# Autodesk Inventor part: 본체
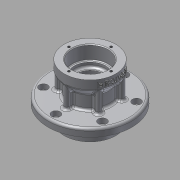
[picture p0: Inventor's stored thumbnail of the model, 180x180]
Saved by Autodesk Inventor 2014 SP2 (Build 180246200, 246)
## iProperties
Created: 2024-04
Part Number: 본체
Material: 알루미늄 6061
Document SubType Name: Modeling
Designer: Administrator
Density: 2.71 g/cm^3
Appearance: 알루미늄 - 평지
Mass: 492.903 g
Surface Area: 449.917 cm^2
Volume: 181.883 cm^3
Author: Administrator
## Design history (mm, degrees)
sketch "스케치1"
  geometry: L1 (-76.3, 0)-(76.3, 0) reference; L2 (0, -76.3)-(0, 76.3) reference; C1 r 54.5 at (0, 0); 1 further point
  constraints: 1 centre point, 1 coincident
  dimensions: "d0" = 109 diameter of C1
extrude "돌출1" new body sketch "스케치1" distance "d1" = 10; taper "d2" = 0 deg
sketch "스케치2"
  geometry: C1 r 54.5 at (0, 0) reference; C2 r 38.5 at (0, 0)
  constraints: 1 centre point, 1 coincident
  dimensions: "d3" = 77 diameter of C2
extrude "돌출2" join sketch "스케치2" distance "d4" = 5; taper "d5" = 0 deg
sketch "스케치3"
  geometry: C1 r 38.5 at (0, 0) reference; C2 r 33.5 at (0, 0)
  constraints: 1 centre point, 1 coincident
  dimensions: "d6" = 67 diameter of C2
extrude "돌출3" join sketch "스케치3" distance "d7" = 15; taper "d8" = 0 deg
node "작업 평면1"
sketch "스케치8"
  geometry: L1 (0, 0)-(0, 72.039); L2 (54.5, 10)-(-54.5, 10) reference; L3 (25.5, 10)-(25.5, 28.121); L4 (25.5, 28.121)-(33.5, 38); L5 (33.5, 38)-(33.5, 50); L6 (33.5, 50)-(0, 50); L7 (25.5, 10)-(0, 10); L8 (0, 50)-(0, 10)
  constraints: 14 end point, 2 perpendicular, 2 point on line, 1 collinear, 1 midpoint, 1 parallel, 1 vertical
  dimensions: "d21" = 67 diameter of L5.end L1; "d22" = 12 distance of L4.end L5.end; "d23" = 39 deg angle of L5 L4; "d24" = 40 distance from line of L3.start L6; "d25" = 51 diameter of L3 L1
revolve "회전1" sketch "스케치8" stored, may be unused: angle "d26" = 90 deg
node "작업 평면2"
sketch "스케치9"
  geometry: L1 (-76.3, 0)-(76.3, 0) reference; L2 (0, -76.3)-(0, 76.3) reference; L3 (0, 20.5)-(0, 30.5); L4 (3, 20.5)-(3, 30.5); L5 (-3, 30.5)-(-3, 20.5); L6 (-13.675, 33.5)-(11.062, 33.5); L7 (-16.254, 12.848)-(-24.914, 17.848); L8 (-27.914, 12.652)-(-19.254, 7.652); L9 (-19.254, -7.652)-(-27.914, -12.652); L10 (-24.914, -17.848)-(-16.254, -12.848); L11 (-3, -20.5)-(-3, -30.5); L12 (3, -30.5)-(3, -20.5); L13 (16.254, -12.848)-(24.914, -17.848); L14 (27.914, -12.652)-(19.254, -7.652); L15 (19.254, 7.652)-(27.914, 12.652); L16 (24.914, 17.848)-(16.254, 12.848); A1 r 3 centre (0, 20.5) between (-3, 20.5) and (3, 20.5); A2 r 3 centre (0, 30.5) between (3, 30.5) and (-3, 30.5); A3 r 3 centre (-26.414, 15.25) between (-24.914, 17.848) and (-27.914, 12.652); A4 r 3 centre (-17.754, 10.25) between (-19.254, 7.652) and (-16.254, 12.848); A5 r 3 centre (-26.414, -15.25) between (-27.914, -12.652) and (-24.914, -17.848); A6 r 3 centre (-17.754, -10.25) between (-16.254, -12.848) and (-19.254, -7.652); A7 r 3 centre (0, -30.5) between (-3, -30.5) and (3, -30.5); A8 r 3 centre (0, -20.5) between (3, -20.5) and (-3, -20.5); A9 r 3 centre (26.414, -15.25) between (24.914, -17.848) and (27.914, -12.652); A10 r 3 centre (17.754, -10.25) between (19.254, -7.652) and (16.254, -12.848); A11 r 3 centre (26.414, 15.25) between (27.914, 12.652) and (24.914, 17.848); A12 r 3 centre (17.754, 10.25) between (16.254, 12.848) and (19.254, 7.652); 3 further points
  constraints: 30 end point, 24 point on circle, 12 centre point, 5 tangent, 2 point on line, 1 midpoint, 1 parallel, 1 perpendicular, 1 vertical alignment, 62 other
  dimensions: "d36" = 6 diameter of A2; "d37" = 33.5 distance from line of point (0, 0) L6; "d40" = 360 deg dimension on point (0, 0) L4.start (derived)
extrude "돌출5" join sketch "스케치9" stored distance "d42" = 0; taper "d43" = 0 deg
extrude "돌출6" join sketch "스케치9" stored distance "d44" = 20; taper "d45" = 0 deg
sketch "스케치10"
  geometry: L1 (-33.5, -20)-(33.5, -20) reference; L2 (-33.5, 50)-(33.5, 50) reference; L3 (0, -34)-(0, 64) reference; L4 (23.5, 50)-(0, 50); L5 (0, 50)-(0, 32); L6 (0, 32)-(23.5, 32); L7 (23.5, 32)-(23.5, 50); L8 (20.5, 32)-(0, 32); L9 (0, 32)-(0, 26); L10 (0, 26)-(20.5, 26); L11 (20.5, 26)-(20.5, 32); L12 (16, 26)-(0, 26); L13 (0, 26)-(0, 4); L14 (0, 4)-(16, 4); L15 (16, 4)-(16, 26); L16 (0, 4)-(20.5, 4); L17 (20.5, 4)-(20.5, -2); L18 (20.5, -2)-(0, -2); L19 (0, -2)-(0, 4); L20 (0, -2)-(23.5, -2); L21 (23.5, -2)-(23.5, -20); L22 (23.5, -20)-(0, -20); L23 (0, -20)-(0, -2); 1 further point
  constraints: 40 end point, 10 parallel, 7 point on line, 5 horizontal, 5 perpendicular
  dimensions: "d46" = 47 diameter of L7 L3; "d47" = 18 distance of L6.end L4.start; "d48" = 41 diameter of L11 L3; "d49" = 6 distance of L10.end L8.start; "d50" = 32 diameter of L15 L3; "d51" = 22 distance of L14.end L12.start; "d52" = 41 diameter of L17 L3; "d53" = 6 distance of L16.end L17.end; "d54" = 47 diameter of L21 L3
revolve "회전2" sketch "스케치10" stored, may be unused: angle "d55" = 90 deg
fillet "모깎기1" dims "d56" = 3
fillet "모깎기2" dims "d57" = 3
fillet "모깎기3" dims "d58" = 3
chamfer "모따기1" distance "d59" = 1; stored, may be unused: second distance "d60" = 2, angle "d61" = 45 deg
fillet "모깎기4" dims "d62" = 3
chamfer "모따기2" distance "d63" = 1; stored, may be unused: second distance "d64" = 2, angle "d65" = 45 deg
fillet "모깎기5" dims "d66" = 3
fillet "모깎기6" dims "d67" = 1
fillet "모깎기7" dims "d68" = 3
sketch "스케치12"
  geometry: L1 (-76.3, 0)-(76.3, 0) reference; L2 (0, -76.3)-(0, 76.3) reference; C1 r 51.5 at (0, 0) reference; C2 r 5.5 at (0, 44.5); C3 r 5.5 at (-38.538, 22.25); C4 r 5.5 at (-38.538, -22.25); C5 r 5.5 at (0, -44.5); C6 r 5.5 at (38.538, -22.25); C7 r 5.5 at (38.538, 22.25); A1 r 25.5 centre (0, 0) between (24.273, -7.815) and (24.273, 7.815) reference
  constraints: 6 centre point, 1 point on line, 13 other
  dimensions: "d69" = 11 diameter of C2; "d70" = 44.5 distance of A1.centre C2.centre; "d73" = 360 deg dimension on C1.centre C2.centre (derived)
extrude "돌출7" cut sketch "스케치12" distance "d75" = 6.6; taper "d76" = 0 deg
sketch "스케치13"
  geometry: C1 r 5.5 at (0, 0) reference; C2 r 5.5 at (-38.538, 66.75) reference; C3 r 5.5 at (0, 44.5) reference; C4 r 5.5 at (-77.076, 44.5) reference; C5 r 5.5 at (-77.076, 0) reference; C6 r 5.5 at (-38.538, -22.25) reference; 7 further points
  constraints: 6 coincident
hole "구멍1" sketch "스케치13" at (-77.076, 44.5), (-77.076, 0), (-38.538, -22.25), (0, 0), (0, 44.5), (-38.538, 66.75) diameter "d77" = 6.6; stored, may be unused: countersink angle "d81" = 90 deg, drill point angle "d83" = 0 deg; dims "d78" = 6, "d79" = 4, "d80" = 2, "d82" = 8
sketch "스케치14"
  geometry: L1 (-76.3, 0)-(76.3, 0) reference; L2 (0, -76.3)-(0, 76.3) reference; 4 further points
  constraints: 4 point on line, 2 symmetric about line
  dimensions: "d84" = 55 distance of point (0, 27.5) point (0, -27.5); "d85" = 55 distance of point (-27.5, 0) point (27.5, 0)
hole "구멍2" sketch "스케치14" at (0, 27.5), (0, -27.5), (-27.5, 0), (27.5, 0) diameter "d86" = 3.242; stored, may be unused: countersink angle "d90" = 90 deg, drill point angle "d92" = 0 deg; dims "d87" = 8, "d88" = 4, "d89" = 2, "d91" = 10
sketch "스케치15"
  geometry: L1 (0, -76.3)-(0, 76.3) reference; L2 (76.3, 0)-(-76.3, 0) reference; 4 further points
  constraints: 4 point on line, 2 symmetric about line
  dimensions: "d93" = 55 distance of point (0, -27.5) point (0, 27.5); "d94" = 55 distance of point (-27.5, 0) point (27.5, 0)
hole "구멍3" sketch "스케치15" at (0, 27.5), (0, -27.5), (-27.5, 0), (27.5, 0) diameter "d95" = 3.242; stored, may be unused: countersink angle "d99" = 90 deg, drill point angle "d101" = 0 deg; dims "d96" = 8, "d97" = 4, "d98" = 2, "d100" = 10
node "작업 평면3"
sketch "스케치16"
  geometry: L1 (-33.5, 50)-(33.5, 50) reference; L2 (-76.3, 0)-(76.3, 0) reference; L3 (0, -34)-(0, 64) reference; 2 further points
  constraints: 1 point on line, 1 other
  dimensions: "d103" = 6 distance from line of L1 point (0, 44)
feature "엠보싱1" sketch "스케치16" dims "d0" = 109, "d21" = 67, "d22" = 12, "d23" = 39 deg, "d24" = 40, "d25" = 51, "d104" = 1, "d105" = 0
fillet "모깎기8" dims "d106" = 3
node "솔리드1"
node "투영된 루프2"
node "투영된 루프3"
node "투영된 루프4"
node "투영된 루프5"
node "투영된 루프6"
other parameters: "d27" = 8
